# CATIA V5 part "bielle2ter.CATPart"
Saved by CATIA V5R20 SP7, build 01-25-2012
Part number: bielle2
Bounding box of the stored display mesh (mm): x 0 to 30, y -90 to 117.254, z -10 to 40.322
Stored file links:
  D:\Dropbox\IAO_2012\IAO_2012_991_jambrosino\IAO_2012_991_jambrosino_Catia\Assemblage\bielle2ter.CATPart
  D:\Dropbox\IAO_2012\IAO_2012_991_jambrosino\IAO_2012_991_jambrosino_Catia\Assemblage\Ass_IAO_991_skl.CATProduct
  J:\IAO_Mecanisme_991\IAO_Mecanisme_991_CATIA\skl_bielle_2.CATPart
  J:\IAO_Mecanisme_991\IAO_Mecanisme_991_CATIA\skl_rainure_circulaire.CATPart
  D:\Dropbox\IAO_2012\IAO_2012_991_jambrosino\IAO_2012_991_jambrosino_Catia\Assemblage\bati.CATPart
  D:\Dropbox\IAO_2012\IAO_2012_991_jambrosino\IAO_2012_991_jambrosino_Catia\Assemblage\rainure_circulaire.CATPart
  J:\IAO_Mecanisme_991\IAO_Mecanisme_991_CATIA\skl_bati.CATPart
  D:\Dropbox\IAO_2012\IAO_2012_991_jambrosino\IAO_2012_991_jambrosino_Catia\Assemblage\excentrique.CATPart
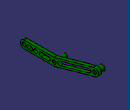
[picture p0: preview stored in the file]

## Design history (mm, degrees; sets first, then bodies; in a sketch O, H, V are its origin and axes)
Set1
  Plane1 "plan_ref_yz": linked copy from another document
  DatumSurface1: linked copy from another document
  Line1: linked copy from another document
  Line2: linked copy from another document
  DatumPoint1: linked copy from another document
  Point1: linked copy from another document
  Line3: linked copy from another document
  DatumPoint2: linked copy from another document
  DatumPoint3: linked copy from another document
  DatumSurface2: linked copy from another document
  DatumCurve1: linked copy from another document
  DatumCurve2: linked copy from another document
Body1 (main body)
  Plane2: type Offset, RefPlane DatumSurface1, Offset 2, reversed
  Sketch1 on Plane2, origin (22, 0, 0), H (0, -1, 0), V (0, 0, 1)
    arc A1 centre (80, 0) radius 10 from (80, -10) to (80.049, 9.9999) ccw
    point P3 (80, 0)
    reference projected point E1 (80, 0) from vertex of DatumPoint1
    line L1 (80, -10) -> (-1.3864, -10)
    point P5 (-1.3864, -10)
    line L2 (-1.3864, -10) -> (-109.9748, 20.6992)
    point P6 (-1.3864, -10)
    point P7 (-109.9748, 20.6992)
    arc A2 centre (-107.2543, 30.322) radius 10 from (-104.5338, 39.9449) to (-109.9748, 20.6992) ccw
    point P8 (-107.2543, 30.322)
    point P9 (-109.9748, 20.6992)
    reference projected point E2 (-107.2543, 30.322) from Point1
    line L3 (80.049, 9.9999) -> (0, 10.3919)
    point P10 (0, 10.3919)
    line L4 (0, 10.3919) -> (-104.5338, 39.9449)
    point P11 (0, 10.3919)
    reference projected line E3 (-107.2543, 30.322) -> (0, 0) from Line1
    reference projected line E4 (-107.2543, 30.322) -> (0, 0) from Line1
    circle A3 centre (80, 0) radius 5
    point P12 (80, 0)
    reference projected point E5 (80, 0) from DatumPoint1
    point P13 (0, 0)
    circle A4 centre (0, 0) radius 5
    reference projected point E6 (0, 0) from vertex of DatumPoint2
    point P14 (-107.2543, 30.322)
    circle A5 centre (-107.2543, 30.322) radius 5
    circle A6 centre (50, 0) radius 5
    point P15 (50, 0)
    reference projected point E7 (50, 0) from vertex of DatumPoint3
    radius A2 = 10
    radius A1 = 10
    radius A4 = 5
    radius A3 = 5
    radius A5 = 5
    radius A6 = 5
    coincidence: P3 E1, P9 L2, P9 P7, P8 E2, P10 V, P11 L3, P11 P10, P6 P5, E5 P12, E6 P13, P8 P14, E7 P15
    tangency: L1 A1, L2 A2, L3 A1, L4 A2
    horizontal: L1 H
    parallelism: L4 E3
    symmetry: L2 L4 E4
  Pad1: profile Sketch1, direction (1, 0, 0), length 8
  Sketch2 on start face of Pad1, origin (22, 0, 0), H (0, -1, 0), V (0, 0, 1)
    circle A1 centre (-107.2543, 30.322) radius 5
    point P1 (-107.2543, 30.322)
    reference projected point E1 (-107.2543, 30.322) from Point1
    reference projected circle E2 centre (-107.2543, 30.322) radius 5 from edge [start face of Pad1 | face of Pad1 from Sketch1.A5]
    coincidence: P1 E1, A1 E2
  Pad2: profile Sketch2, direction (-1, 0, 0), length 12, opposite side length 5
  Sketch3 on start face of Pad1, origin (22, 0, 0), H (0, -1, 0), V (0, 0, 1)
    circle A1 centre (0, 0) radius 5
    reference projected circle E1 centre (0, 0) radius 5 from edge [start face of Pad1 | face of Pad1 from Sketch1.A4]
    coincidence: A1 E1
  Pad3: profile Sketch3, direction (-1, 0, 0), up to DatumSurface2, opposite side length 5
  Sketch4 on end face of Pad2, origin (10, 0, 0), H (0, -1, 0), V (0, 0, 1)
    circle A1 centre (-107.2543, 30.322) radius 7.7913
    point P1 (-107.2543, 30.322)
    reference projected point E1 (-107.2543, 30.322) from Point1
    reference projected curve E2 from edge of DatumCurve2
    distance A1 E2 = 0
    coincidence: P1 E1
  Pad4: profile Sketch4, direction (1, 0, 0), length 10
  Plane3: type Offset, RefPlane DatumSurface1, Offset 0
  Sketch5 on end face of Pad1, origin (30, 0, 0), H (0, 1, 0), V (0, 0, 1)
    line L1 (13.074, 8.8921) -> (91.4598, 31.0527)
    point P2 (91.4598, 31.0527)
    line L2 (15.7945, -0.7307) -> (94.1803, 21.4299)
    point P3 (15.7945, -0.7307)
    point P4 (94.1803, 21.4299)
    construction line L3 (109.3224, 30.9067) -> (-43.1077, -12.1871)
    reference projected line E1 (0, 10.3919) -> (104.5338, 39.9449) from edge [end face of Pad1 | face of Pad1 from Sketch1.L4]
    reference projected line E2 (109.9748, 20.6992) -> (1.3864, -10) from edge [end face of Pad1 | face of Pad1 from Sketch1.L2]
    arc A1 centre (92.82, 26.2413) radius 5 from (94.1803, 21.4299) to (91.4598, 31.0527) ccw
    point P7 (92.82, 26.2413)
    point P8 (91.4598, 31.0527)
    arc A2 centre (14.4343, 4.0807) radius 5 from (13.074, 8.8921) to (15.7945, -0.7307) ccw
    point P9 (14.4343, 4.0807)
    point P10 (15.7945, -0.7307)
    reference projected circle E3 centre (107.2543, 30.322) radius 5 from edge [face of Pad1 from Sketch1.A5 | end face of Pad1]
    reference projected circle E4 centre (0, 0) radius 5 from edge [face of Pad1 from Sketch1.A4 | end face of Pad1]
    construction line L4 (-35.0004, 0.1102) -> (-14.9992, 0.1592)
    point P11 (-35.0004, 0.1102)
    point P12 (-14.9992, 0.1592)
    line L5 (-35.0126, 5.1102) -> (-15.0114, 5.1592)
    line L6 (-14.9869, -4.8408) -> (-34.9882, -4.8898)
    arc A3 centre (-14.9992, 0.1592) radius 5 from (-15.0114, 5.1592) to (-14.9869, -4.8408) cw
    arc A4 centre (-35.0004, 0.1102) radius 5 from (-34.9882, -4.8898) to (-35.0126, 5.1102) cw
    reference projected circle E5 centre (0, 0) radius 5 from edge [face of Pad1 from Sketch1.A4 | end face of Pad1]
    reference projected circle E6 centre (-50, 0) radius 5 from edge [face of Pad1 from Sketch1.A6 | end face of Pad1]
    axis line L7 (-41.1937, 0.095) -> (20.8142, 0.2469)
    reference projected line E7 (-80.049, 9.9999) -> (0, 10.3919) from edge [end face of Pad1 | face of Pad1 from Sketch1.L3]
    reference projected line E8 (1.3864, -10) -> (-80, -10) from edge [end face of Pad1 | face of Pad1 from Sketch1.L1]
    construction line L8 (-68, 0) -> (-61.9998, -0.0669)
    point P19 (-68, 0)
    line L9 (-67.9442, 4.9997) -> (-61.944, 4.9328)
    line L10 (-62.0556, -5.0666) -> (-68.0558, -4.9997)
    arc A5 centre (-61.9998, -0.0669) radius 5 from (-61.944, 4.9328) to (-62.0556, -5.0666) cw
    arc A6 centre (-68, 0) radius 5 from (-68.0558, -4.9997) to (-67.9442, 4.9997) cw
    reference projected circle E9 centre (-50, 0) radius 5 from edge [face of Pad1 from Sketch1.A6 | end face of Pad1]
    reference projected circle E10 centre (-80, 0) radius 5 from edge [face of Pad1 from Sketch1.A3 | end face of Pad1]
    distance L1 L2 = 10
    distance P7 E3 = 10
    distance E4 P9 = 10
    distance L5 L6 = 10
    distance P12 E5 = 10
    distance P11 E6 = 10
    distance L9 L10 = 10
    distance A5 E9 = 2
    distance A6 E10 = 2
    symmetry: E1 E2 L3, L1 L2 L3, E7 E8 L7
    coincidence: P7 L3, P8 L1, A1 P4, P2 P8, P9 L3, P10 L2, P10 P3, L4 L7, P19 H
    tangency: A1 L1, A2 L1, A3 L5, A4 L5, A3 L6, A4 L6, L8 A2, A5 L9, A6 L9, A5 L10, A6 L10
  Pocket1: profile Sketch5, direction (-1, 0, 0), length 10
  Point2: type Center, Curve edge [face of Pad4 from Sketch4.A1 | face of Pad4]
